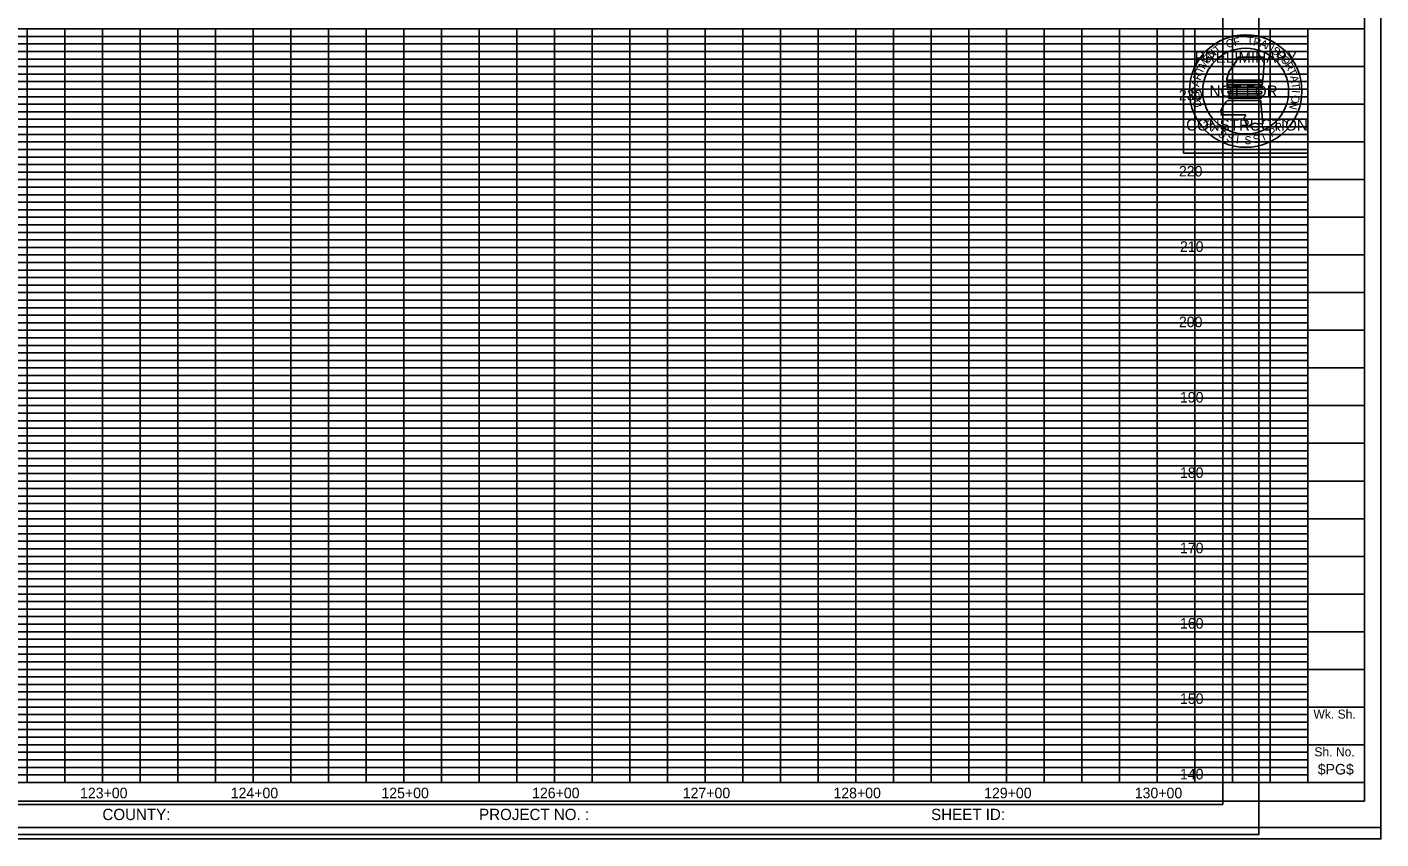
# Model space of a CAD drawing. Extents: x 1383694 to 1386843, y 1973227 to 1975727.
# Drawn here: x 1385944 to 1386843, y 1974440 to 1974979 of the extents above; entities that cross this region are included whole.
import ezdxf

# ---------------------------------------------------------------- set-up
doc = ezdxf.new("R2010")
doc.units = 0
for name, color, linetype in [('Default', 7, 'Continuous'), ('R_Border', 7, 'Continuous'), ('R_Grid', 7, 'Continuous'), ('R_No Plot', 7, 'Continuous'), ('SHEET_BORDER', 7, 'Continuous'), ('SHEET_BORDER_GRIDS', 7, 'Continuous'), ('SHEET_BORDER_TX', 7, 'Continuous'), ('SHEET_LOGO', 7, 'Continuous'), ('SHEET_PAGE_NUMBER', 7, 'Continuous'), ('SHEET_PLOTTING_SHAPE', 7, 'Continuous'), ('SHEET_PRELIM', 7, 'Continuous')]:
    doc.layers.add(name, color=color, linetype=linetype)

msp = doc.modelspace()

# ---------------------------------------------------------------- linework, layer by layer
at = {"layer": 'R_Border'}
for p, q in [((1386737.83, 1974462.74), (1386737.83, 1975490.04)), ((1386737.83, 1974977.44), (1385156.93, 1974977.44)), ((1385944.23, 1974477.44), (1385944.23, 1974977.44)), ((1385994.23, 1974477.44), (1385994.23, 1974977.44)), ((1386044.23, 1974477.44), (1386044.23, 1974977.44)), ((1386094.23, 1974477.44), (1386094.23, 1974977.44)), ((1386144.23, 1974477.44), (1386144.23, 1974977.44)), ((1386194.23, 1974477.44), (1386194.23, 1974977.44)), ((1386244.23, 1974477.44), (1386244.23, 1974977.44)), ((1386294.23, 1974477.44), (1386294.23, 1974977.44)), ((1386344.23, 1974477.44), (1386344.23, 1974977.44)), ((1386394.23, 1974477.44), (1386394.23, 1974977.44)), ((1386444.23, 1974477.44), (1386444.23, 1974977.44)), ((1386494.23, 1974477.44), (1386494.23, 1974977.44)), ((1386544.23, 1974477.44), (1386544.23, 1974977.44)), ((1386594.23, 1974477.44), (1386594.23, 1974977.44)), ((1386644.23, 1974477.44), (1386644.23, 1974977.44)), ((1386694.23, 1974477.44), (1386694.23, 1974977.44)), ((1386737.83, 1974927.44), (1385156.93, 1974927.44)), ((1386737.83, 1974877.44), (1385156.93, 1974877.44)), ((1386737.83, 1974827.44), (1385156.93, 1974827.44)), ((1386737.83, 1974777.44), (1385156.93, 1974777.44)), ((1386737.83, 1974727.44), (1385156.93, 1974727.44)), ((1386737.83, 1974677.44), (1385156.93, 1974677.44)), ((1386737.83, 1974627.44), (1385156.93, 1974627.44)), ((1386737.83, 1974577.44), (1385156.93, 1974577.44)), ((1386737.83, 1974527.44), (1385156.93, 1974527.44)), ((1386737.83, 1974477.44), (1385156.93, 1974477.44)), ((1386737.83, 1974462.74), (1385156.93, 1974462.74))]:
    msp.add_line(p, q, dxfattribs=at)
at = {"layer": 'R_Grid'}
for p, q in [((1386694.23, 1974972.44), (1385194.23, 1974972.44)), ((1385969.23, 1974477.44), (1385969.23, 1974977.44)), ((1386019.23, 1974477.44), (1386019.23, 1974977.44)), ((1386069.23, 1974477.44), (1386069.23, 1974977.44)), ((1386119.23, 1974477.44), (1386119.23, 1974977.44)), ((1386169.23, 1974477.44), (1386169.23, 1974977.44)), ((1386219.23, 1974477.44), (1386219.23, 1974977.44)), ((1386269.23, 1974477.44), (1386269.23, 1974977.44)), ((1386319.23, 1974477.44), (1386319.23, 1974977.44)), ((1386369.23, 1974477.44), (1386369.23, 1974977.44)), ((1386419.23, 1974477.44), (1386419.23, 1974977.44)), ((1386469.23, 1974477.44), (1386469.23, 1974977.44)), ((1386519.23, 1974477.44), (1386519.23, 1974977.44)), ((1386569.23, 1974477.44), (1386569.23, 1974977.44)), ((1386619.23, 1974477.44), (1386619.23, 1974977.44)), ((1386669.23, 1974477.44), (1386669.23, 1974977.44)), ((1386694.23, 1974967.44), (1385194.23, 1974967.44)), ((1386694.23, 1974962.44), (1385194.23, 1974962.44)), ((1386694.23, 1974957.44), (1385194.23, 1974957.44)), ((1386694.23, 1974952.44), (1385194.23, 1974952.44)), ((1386694.23, 1974947.44), (1385194.23, 1974947.44)), ((1386694.23, 1974942.44), (1385194.23, 1974942.44)), ((1386694.23, 1974937.44), (1385194.23, 1974937.44)), ((1386694.23, 1974932.44), (1385194.23, 1974932.44)), ((1386694.23, 1974922.44), (1385194.23, 1974922.44)), ((1386694.23, 1974917.44), (1385194.23, 1974917.44)), ((1386694.23, 1974912.44), (1385194.23, 1974912.44)), ((1386694.23, 1974907.44), (1385194.23, 1974907.44)), ((1386694.23, 1974902.44), (1385194.23, 1974902.44)), ((1386694.23, 1974897.44), (1385194.23, 1974897.44)), ((1386694.23, 1974892.44), (1385194.23, 1974892.44)), ((1386694.23, 1974887.44), (1385194.23, 1974887.44)), ((1386694.23, 1974882.44), (1385194.23, 1974882.44)), ((1386694.23, 1974872.44), (1385194.23, 1974872.44)), ((1386694.23, 1974867.44), (1385194.23, 1974867.44)), ((1386694.23, 1974862.44), (1385194.23, 1974862.44)), ((1386694.23, 1974857.44), (1385194.23, 1974857.44)), ((1386694.23, 1974852.44), (1385194.23, 1974852.44)), ((1386694.23, 1974847.44), (1385194.23, 1974847.44)), ((1386694.23, 1974842.44), (1385194.23, 1974842.44)), ((1386694.23, 1974837.44), (1385194.23, 1974837.44)), ((1386694.23, 1974832.44), (1385194.23, 1974832.44)), ((1386694.23, 1974822.44), (1385194.23, 1974822.44)), ((1386694.23, 1974817.44), (1385194.23, 1974817.44)), ((1386694.23, 1974812.44), (1385194.23, 1974812.44)), ((1386694.23, 1974807.44), (1385194.23, 1974807.44)), ((1386694.23, 1974802.44), (1385194.23, 1974802.44)), ((1386694.23, 1974797.44), (1385194.23, 1974797.44)), ((1386694.23, 1974792.44), (1385194.23, 1974792.44)), ((1386694.23, 1974787.44), (1385194.23, 1974787.44)), ((1386694.23, 1974782.44), (1385194.23, 1974782.44)), ((1386694.23, 1974772.44), (1385194.23, 1974772.44)), ((1386694.23, 1974767.44), (1385194.23, 1974767.44)), ((1386694.23, 1974762.44), (1385194.23, 1974762.44)), ((1386694.23, 1974757.44), (1385194.23, 1974757.44)), ((1386694.23, 1974752.44), (1385194.23, 1974752.44)), ((1386694.23, 1974747.44), (1385194.23, 1974747.44)), ((1386694.23, 1974742.44), (1385194.23, 1974742.44)), ((1386694.23, 1974737.44), (1385194.23, 1974737.44)), ((1386694.23, 1974732.44), (1385194.23, 1974732.44)), ((1386694.23, 1974722.44), (1385194.23, 1974722.44)), ((1386694.23, 1974717.44), (1385194.23, 1974717.44)), ((1386694.23, 1974712.44), (1385194.23, 1974712.44)), ((1386694.23, 1974707.44), (1385194.23, 1974707.44)), ((1386694.23, 1974702.44), (1385194.23, 1974702.44)), ((1386694.23, 1974697.44), (1385194.23, 1974697.44)), ((1386694.23, 1974692.44), (1385194.23, 1974692.44)), ((1386694.23, 1974687.44), (1385194.23, 1974687.44)), ((1386694.23, 1974682.44), (1385194.23, 1974682.44)), ((1386694.23, 1974672.44), (1385194.23, 1974672.44)), ((1386694.23, 1974667.44), (1385194.23, 1974667.44)), ((1386694.23, 1974662.44), (1385194.23, 1974662.44)), ((1386694.23, 1974657.44), (1385194.23, 1974657.44)), ((1386694.23, 1974652.44), (1385194.23, 1974652.44)), ((1386694.23, 1974647.44), (1385194.23, 1974647.44)), ((1386694.23, 1974642.44), (1385194.23, 1974642.44)), ((1386694.23, 1974637.44), (1385194.23, 1974637.44)), ((1386694.23, 1974632.44), (1385194.23, 1974632.44)), ((1386694.23, 1974622.44), (1385194.23, 1974622.44)), ((1386694.23, 1974617.44), (1385194.23, 1974617.44)), ((1386694.23, 1974612.44), (1385194.23, 1974612.44)), ((1386694.23, 1974607.44), (1385194.23, 1974607.44)), ((1386694.23, 1974602.44), (1385194.23, 1974602.44)), ((1386694.23, 1974597.44), (1385194.23, 1974597.44)), ((1386694.23, 1974592.44), (1385194.23, 1974592.44)), ((1386694.23, 1974587.44), (1385194.23, 1974587.44)), ((1386694.23, 1974582.44), (1385194.23, 1974582.44)), ((1386694.23, 1974572.44), (1385194.23, 1974572.44)), ((1386694.23, 1974567.44), (1385194.23, 1974567.44)), ((1386694.23, 1974562.44), (1385194.23, 1974562.44)), ((1386694.23, 1974557.44), (1385194.23, 1974557.44)), ((1386694.23, 1974552.44), (1385194.23, 1974552.44)), ((1386694.23, 1974547.44), (1385194.23, 1974547.44)), ((1386694.23, 1974542.44), (1385194.23, 1974542.44)), ((1386694.23, 1974537.44), (1385194.23, 1974537.44)), ((1386694.23, 1974532.44), (1385194.23, 1974532.44)), ((1386694.23, 1974522.44), (1385194.23, 1974522.44)), ((1386694.23, 1974517.44), (1385194.23, 1974517.44)), ((1386694.23, 1974512.44), (1385194.23, 1974512.44)), ((1386694.23, 1974507.44), (1385194.23, 1974507.44)), ((1386694.23, 1974502.44), (1385194.23, 1974502.44)), ((1386694.23, 1974497.44), (1385194.23, 1974497.44)), ((1386694.23, 1974492.44), (1385194.23, 1974492.44)), ((1386694.23, 1974487.44), (1385194.23, 1974487.44)), ((1386694.23, 1974482.44), (1385194.23, 1974482.44))]:
    msp.add_line(p, q, dxfattribs=at)
at = {"layer": 'R_No Plot'}
msp.add_line((1385094.93, 1974442.85), (1386761.6, 1974442.85), dxfattribs=at)
msp.add_lwpolyline([(1385094.93, 1975509.53), (1386761.63, 1975509.53), (1386761.63, 1974442.85), (1385094.93, 1974442.85)], close=True, dxfattribs=at)
at = {"layer": 'SHEET_BORDER'}
for p, q in [((1386831.73, 1975514.89), (1386831.73, 1974464.94)), ((1385156.73, 1974977.44), (1386831.73, 1974977.44)), ((1386794.23, 1974977.44), (1386794.23, 1974477.44)), ((1386794.23, 1974527.44), (1386831.73, 1974527.44)), ((1386794.23, 1974502.44), (1386831.73, 1974502.44)), ((1385194.23, 1974477.44), (1386831.73, 1974477.44)), ((1385244.23, 1974464.94), (1386831.73, 1974464.94)), ((1385082.73, 1974447.44), (1386842.73, 1974447.44))]:
    msp.add_line(p, q, dxfattribs=at)
for points in [[(1385156.73, 1975514.94), (1385156.73, 1974977.44), (1386831.73, 1974977.44), (1386831.73, 1975473.74), (1386695.93, 1975473.74), (1386695.93, 1975514.94)], [(1385194.23, 1974477.44), (1385194.23, 1974977.44), (1386794.23, 1974977.44), (1386794.23, 1974477.44)]]:
    msp.add_lwpolyline(points, close=True, dxfattribs=at)
at = {"layer": 'SHEET_BORDER_GRIDS'}
for p, q in [((1385194.23, 1974972.44), (1386794.23, 1974972.44)), ((1385969.23, 1974977.44), (1385969.23, 1974477.44)), ((1385994.23, 1974477.44), (1385994.23, 1974977.44)), ((1386019.23, 1974977.44), (1386019.23, 1974477.44)), ((1386044.23, 1974477.44), (1386044.23, 1974977.44)), ((1386069.23, 1974977.44), (1386069.23, 1974477.44)), ((1386094.23, 1974477.44), (1386094.23, 1974977.44)), ((1386119.23, 1974977.44), (1386119.23, 1974477.44)), ((1386144.23, 1974477.44), (1386144.23, 1974977.44)), ((1386169.23, 1974977.44), (1386169.23, 1974477.44)), ((1386194.23, 1974477.44), (1386194.23, 1974977.44)), ((1386219.23, 1974977.44), (1386219.23, 1974477.44)), ((1386244.23, 1974477.44), (1386244.23, 1974977.44)), ((1386269.23, 1974977.44), (1386269.23, 1974477.44)), ((1386294.23, 1974477.44), (1386294.23, 1974977.44)), ((1386319.23, 1974977.44), (1386319.23, 1974477.44)), ((1386344.23, 1974477.44), (1386344.23, 1974977.44)), ((1386369.23, 1974977.44), (1386369.23, 1974477.44)), ((1386394.23, 1974477.44), (1386394.23, 1974977.44)), ((1386419.23, 1974977.44), (1386419.23, 1974477.44)), ((1386444.23, 1974477.44), (1386444.23, 1974977.44)), ((1386469.23, 1974977.44), (1386469.23, 1974477.44)), ((1386494.23, 1974477.44), (1386494.23, 1974977.44)), ((1386519.23, 1974977.44), (1386519.23, 1974477.44)), ((1386544.23, 1974477.44), (1386544.23, 1974977.44)), ((1386569.23, 1974977.44), (1386569.23, 1974477.44)), ((1386594.23, 1974477.44), (1386594.23, 1974977.44)), ((1386619.23, 1974977.44), (1386619.23, 1974477.44)), ((1386644.23, 1974477.44), (1386644.23, 1974977.44)), ((1386669.23, 1974977.44), (1386669.23, 1974477.44)), ((1386694.23, 1974977.44), (1386694.23, 1974477.44)), ((1386719.23, 1974977.44), (1386719.23, 1974477.44)), ((1386744.23, 1974977.44), (1386744.23, 1974477.44)), ((1386769.23, 1974977.44), (1386769.23, 1974477.44)), ((1385194.23, 1974967.44), (1386794.23, 1974967.44)), ((1385194.23, 1974962.44), (1386794.23, 1974962.44)), ((1385156.73, 1974952.44), (1386831.73, 1974952.44)), ((1385194.23, 1974957.44), (1386794.23, 1974957.44)), ((1385194.23, 1974947.44), (1386794.23, 1974947.44)), ((1385194.23, 1974942.44), (1386794.23, 1974942.44)), ((1385194.23, 1974937.44), (1386794.23, 1974937.44)), ((1385156.73, 1974927.44), (1386831.73, 1974927.44)), ((1385194.23, 1974932.44), (1386794.23, 1974932.44)), ((1385194.23, 1974922.44), (1386794.23, 1974922.44)), ((1385194.23, 1974917.44), (1386794.23, 1974917.44)), ((1385194.23, 1974912.44), (1386794.23, 1974912.44)), ((1385194.23, 1974907.44), (1386794.23, 1974907.44)), ((1385156.73, 1974902.44), (1386831.73, 1974902.44)), ((1385194.23, 1974897.44), (1386794.23, 1974897.44)), ((1385194.23, 1974892.44), (1386794.23, 1974892.44)), ((1385194.23, 1974887.44), (1386794.23, 1974887.44)), ((1385194.23, 1974882.44), (1386794.23, 1974882.44)), ((1385156.73, 1974877.44), (1386831.73, 1974877.44)), ((1385194.23, 1974872.44), (1386794.23, 1974872.44)), ((1385194.23, 1974867.44), (1386794.23, 1974867.44)), ((1385194.23, 1974862.44), (1386794.23, 1974862.44)), ((1385194.23, 1974857.44), (1386794.23, 1974857.44)), ((1385156.73, 1974852.44), (1386831.73, 1974852.44)), ((1385194.23, 1974847.44), (1386794.23, 1974847.44)), ((1385194.23, 1974842.44), (1386794.23, 1974842.44)), ((1385194.23, 1974837.44), (1386794.23, 1974837.44)), ((1385156.73, 1974827.44), (1386831.73, 1974827.44)), ((1385194.23, 1974832.44), (1386794.23, 1974832.44)), ((1385194.23, 1974822.44), (1386794.23, 1974822.44)), ((1385194.23, 1974817.44), (1386794.23, 1974817.44)), ((1385194.23, 1974812.44), (1386794.23, 1974812.44)), ((1385156.73, 1974802.44), (1386831.73, 1974802.44)), ((1385194.23, 1974807.44), (1386794.23, 1974807.44)), ((1385194.23, 1974797.44), (1386794.23, 1974797.44)), ((1385194.23, 1974792.44), (1386794.23, 1974792.44)), ((1385194.23, 1974787.44), (1386794.23, 1974787.44)), ((1385194.23, 1974782.44), (1386794.23, 1974782.44)), ((1385156.73, 1974777.44), (1386831.73, 1974777.44)), ((1385194.23, 1974772.44), (1386794.23, 1974772.44)), ((1385194.23, 1974767.44), (1386794.23, 1974767.44)), ((1385194.23, 1974762.44), (1386794.23, 1974762.44)), ((1385194.23, 1974757.44), (1386794.23, 1974757.44)), ((1385156.73, 1974752.44), (1386831.73, 1974752.44)), ((1385194.23, 1974747.44), (1386794.23, 1974747.44)), ((1385194.23, 1974742.44), (1386794.23, 1974742.44)), ((1385194.23, 1974737.44), (1386794.23, 1974737.44)), ((1385156.73, 1974727.44), (1386831.73, 1974727.44)), ((1385194.23, 1974732.44), (1386794.23, 1974732.44)), ((1385194.23, 1974722.44), (1386794.23, 1974722.44)), ((1385194.23, 1974717.44), (1386794.23, 1974717.44)), ((1385194.23, 1974712.44), (1386794.23, 1974712.44)), ((1385156.73, 1974702.44), (1386831.73, 1974702.44)), ((1385194.23, 1974707.44), (1386794.23, 1974707.44)), ((1385194.23, 1974697.44), (1386794.23, 1974697.44)), ((1385194.23, 1974692.44), (1386794.23, 1974692.44)), ((1385194.23, 1974687.44), (1386794.23, 1974687.44)), ((1385194.23, 1974682.44), (1386794.23, 1974682.44)), ((1385156.73, 1974677.44), (1386831.73, 1974677.44)), ((1385194.23, 1974672.44), (1386794.23, 1974672.44)), ((1385194.23, 1974667.44), (1386794.23, 1974667.44)), ((1385194.23, 1974662.44), (1386794.23, 1974662.44)), ((1385194.23, 1974657.44), (1386794.23, 1974657.44)), ((1385156.73, 1974652.44), (1386831.73, 1974652.44)), ((1385194.23, 1974647.44), (1386794.23, 1974647.44)), ((1385194.23, 1974642.44), (1386794.23, 1974642.44)), ((1385194.23, 1974637.44), (1386794.23, 1974637.44)), ((1385194.23, 1974632.44), (1386794.23, 1974632.44)), ((1385156.73, 1974627.44), (1386831.73, 1974627.44)), ((1385194.23, 1974622.44), (1386794.23, 1974622.44)), ((1385194.23, 1974617.44), (1386794.23, 1974617.44)), ((1385194.23, 1974612.44), (1386794.23, 1974612.44)), ((1385156.73, 1974602.44), (1386831.73, 1974602.44)), ((1385194.23, 1974607.44), (1386794.23, 1974607.44)), ((1385194.23, 1974597.44), (1386794.23, 1974597.44)), ((1385194.23, 1974592.44), (1386794.23, 1974592.44)), ((1385194.23, 1974587.44), (1386794.23, 1974587.44)), ((1385156.73, 1974577.44), (1386831.73, 1974577.44)), ((1385194.23, 1974582.44), (1386794.23, 1974582.44)), ((1385194.23, 1974572.44), (1386794.23, 1974572.44)), ((1385194.23, 1974567.44), (1386794.23, 1974567.44)), ((1385194.23, 1974562.44), (1386794.23, 1974562.44)), ((1385194.23, 1974557.44), (1386794.23, 1974557.44)), ((1385156.73, 1974552.44), (1386831.73, 1974552.44)), ((1385194.23, 1974547.44), (1386794.23, 1974547.44)), ((1385194.23, 1974542.44), (1386794.23, 1974542.44)), ((1385194.23, 1974537.44), (1386794.23, 1974537.44)), ((1385194.23, 1974532.44), (1386794.23, 1974532.44)), ((1385156.73, 1974527.44), (1386794.23, 1974527.44)), ((1385194.23, 1974522.44), (1386794.23, 1974522.44)), ((1385194.23, 1974517.44), (1386794.23, 1974517.44)), ((1385194.23, 1974512.44), (1386794.23, 1974512.44)), ((1385156.73, 1974502.44), (1386794.23, 1974502.44)), ((1385194.23, 1974507.44), (1386794.23, 1974507.44)), ((1385194.23, 1974497.44), (1386794.23, 1974497.44)), ((1385194.23, 1974492.44), (1386794.23, 1974492.44)), ((1385194.23, 1974487.44), (1386794.23, 1974487.44)), ((1385194.23, 1974482.44), (1386794.23, 1974482.44))]:
    msp.add_line(p, q, dxfattribs=at)
msp.add_lwpolyline([(1385194.23, 1974627.44), (1385194.23, 1974477.44), (1386794.23, 1974477.44), (1386794.23, 1974627.44)], close=True, dxfattribs=at)
at = {"layer": 'SHEET_LOGO'}
for points in [[(1386711.73, 1974894.94), (1386794.23, 1974894.94), (1386794.23, 1974977.44), (1386711.73, 1974977.44)], [(1386765.54, 1974957.9), (1386764.85, 1974958.03), (1386764.76, 1974958.59), (1386747.82, 1974958.59), (1386747.99, 1974957.78), (1386745.97, 1974955.2), (1386745.15, 1974953.09), (1386741.93, 1974949.3), (1386740.55, 1974944.27), (1386740.55, 1974943.37), (1386764.29, 1974943.37)], [(1386740.6, 1974941.78), (1386764.16, 1974941.78), (1386763.99, 1974940.4), (1386740.6, 1974940.4)], [(1386740.68, 1974938.86), (1386763.86, 1974938.86), (1386763.82, 1974937.48), (1386740.9, 1974937.48)], [(1386763.64, 1974935.8), (1386763.52, 1974934.43), (1386741.71, 1974934.43), (1386741.11, 1974935.89)], [(1386740.9, 1974929.91), (1386739.87, 1974928.92), (1386738.06, 1974926.3), (1386736.34, 1974922.69), (1386737.16, 1974921.35), (1386736.68, 1974920.41), (1386752.81, 1974920.41), (1386752.85, 1974919.59), (1386752.03, 1974918.73), (1386751.82, 1974917.44), (1386752.81, 1974915.94), (1386753.88, 1974912.97), (1386755, 1974912.84), (1386756.38, 1974914), (1386759.26, 1974914.82), (1386760.76, 1974914.35), (1386764.42, 1974914.6), (1386763.04, 1974929.14), (1386763.13, 1974929.91)], [(1386742.49, 1974932.84), (1386742.49, 1974932.71), (1386741.71, 1974931.89), (1386741.63, 1974931.46), (1386763.26, 1974931.46), (1386763.39, 1974932.84)]]:
    msp.add_lwpolyline(points, close=True, dxfattribs=at)
for radius in [37.32, 28.48]:
    msp.add_circle((1386752.98, 1974936.19), radius, dxfattribs=at)
at = {"layer": 'SHEET_PLOTTING_SHAPE'}
msp.add_lwpolyline([(1385112.73, 1974439.94), (1386842.73, 1974439.94), (1386842.73, 1975539.94), (1385112.73, 1975539.94)], close=True, dxfattribs=at)
at = {"layer": 'SHEET_PRELIM'}
msp.add_lwpolyline([(1386711.73, 1974894.94), (1386794.23, 1974894.94), (1386794.23, 1974977.44), (1386711.73, 1974977.44)], close=True, dxfattribs=at)

# ---------------------------------------------------------------- texts
at = {"layer": 'Default'}
for s, p in [('230', (1386708.66, 1974930.03)), ('220', (1386708.66, 1974879.51)), ('210', (1386709.36, 1974829.51)), ('200', (1386708.66, 1974779.51)), ('190', (1386709.36, 1974729.51)), ('180', (1386709.36, 1974679.51)), ('170', (1386709.36, 1974629.51)), ('160', (1386709.36, 1974579.51)), ('150', (1386709.36, 1974529.51)), ('140', (1386709.36, 1974479.44)), ('123+00', (1385979.38, 1974466.92)), ('124+00', (1386079.38, 1974466.92)), ('125+00', (1386179.38, 1974466.92)), ('126+00', (1386279.38, 1974466.92)), ('127+00', (1386379.38, 1974466.92)), ('128+00', (1386479.38, 1974466.92)), ('129+00', (1386579.38, 1974466.92)), ('130+00', (1386679.38, 1974466.92))]:
    msp.add_text(s, height=7, dxfattribs=at).set_placement(p)
at = {"layer": 'SHEET_BORDER'}
msp.add_text('Sh. No.', height=6, dxfattribs=at).set_placement((1386798.58, 1974494.74))
at = {"layer": 'SHEET_BORDER_TX'}
for s, height, p in [('Wk. Sh.', 6, (1386797.93, 1974519.74)), ('Sh. No.', 6, (1386798.58, 1974494.74)), ('COUNTY:', 7.5, (1385994.23, 1974452.44)), ('PROJECT NO. :', 7.5, (1386244.23, 1974452.44)), ('SHEET ID:', 7.5, (1386544.23, 1974452.44))]:
    msp.add_text(s, height=height, dxfattribs=at).set_placement(p)
at = {"layer": 'SHEET_LOGO'}
for s, rotation, p in [('O', 18.18791, (1386740.83, 1974964.57)), ('F', 11.39008, (1386745.41, 1974965.98)), ('T', 357.79443, (1386753.7, 1974966.91)), ('R', 350.9966, (1386757.73, 1974966.53)), ('A', 337.40094, (1386761.82, 1974965.82)), ('E', 52.17705, (1386728.23, 1974954.48)), ('N', 45.37922, (1386730.63, 1974957.21)), ('T', 38.58139, (1386734.12, 1974960.42)), ('N', 330.60312, (1386765.53, 1974964.35)), ('S', 323.80529, (1386769.73, 1974962)), ('P', 317.00746, (1386772.89, 1974959.6)), ('T', 65.77271, (1386724.19, 1974947.01)), ('M', 58.97488, (1386725.61, 1974950.28)), ('O', 310.20963, (1386775.62, 1974956.99)), ('R', 303.41181, (1386778.45, 1974953.33)), ('T', 296.61398, (1386780.63, 1974949.63)), ('A', 79.36836, (1386722.18, 1974938.61)), ('R', 72.57053, (1386722.89, 1974942.92)), ('A', 283.01832, (1386782.27, 1974945.92)), ('P', 92.96402, (1386722.29, 1974934.47)), ('E', 99.76184, (1386722.83, 1974930.48)), ('T', 276.22049, (1386783.31, 1974941.61)), ('I', 269.42267, (1386783.74, 1974936.81)), ('D', 106.55967, (1386723.98, 1974926.07)), ('N', 255.82701, (1386782.98, 1974929.56)), ('O', 262.62484, (1386783.63, 1974933.76)), ('M', 309.11023, (1386724.41, 1974915.54)), ('I', 48.97748, (1386780.31, 1974913.91)), ('I', 321.59363, (1386729.48, 1974909.93)), ('S', 327.83534, (1386734.17, 1974906.49)), ('S', 340.31874, (1386739.68, 1974903.55)), ('I', 352.80215, (1386746.28, 1974901.58)), ('S', 11.52726, (1386758.39, 1974901.37)), ('I', 24.01067, (1386764.98, 1974903)), ('P', 30.25237, (1386770.11, 1974905.46)), ('P', 42.73578, (1386775.34, 1974908.95)), ('S', 359.04385, (1386752.06, 1974900.98))]:
    msp.add_text(s, height=5.31, rotation=rotation, dxfattribs=at).set_placement(p)
at = {"layer": 'SHEET_PAGE_NUMBER'}
msp.add_text('$PG$', height=7, dxfattribs=at).set_placement((1386800.8, 1974482.69))
at = {"layer": 'SHEET_PRELIM'}
for s, p in [('PRELIMINARY', (1386719.16, 1974954.94)), ('NOT FOR', (1386728.98, 1974932.44)), ('CONSTRUCTION', (1386713.43, 1974909.94))]:
    msp.add_text(s, height=7.5, dxfattribs=at).set_placement(p)

doc.saveas('drawing.dxf')
